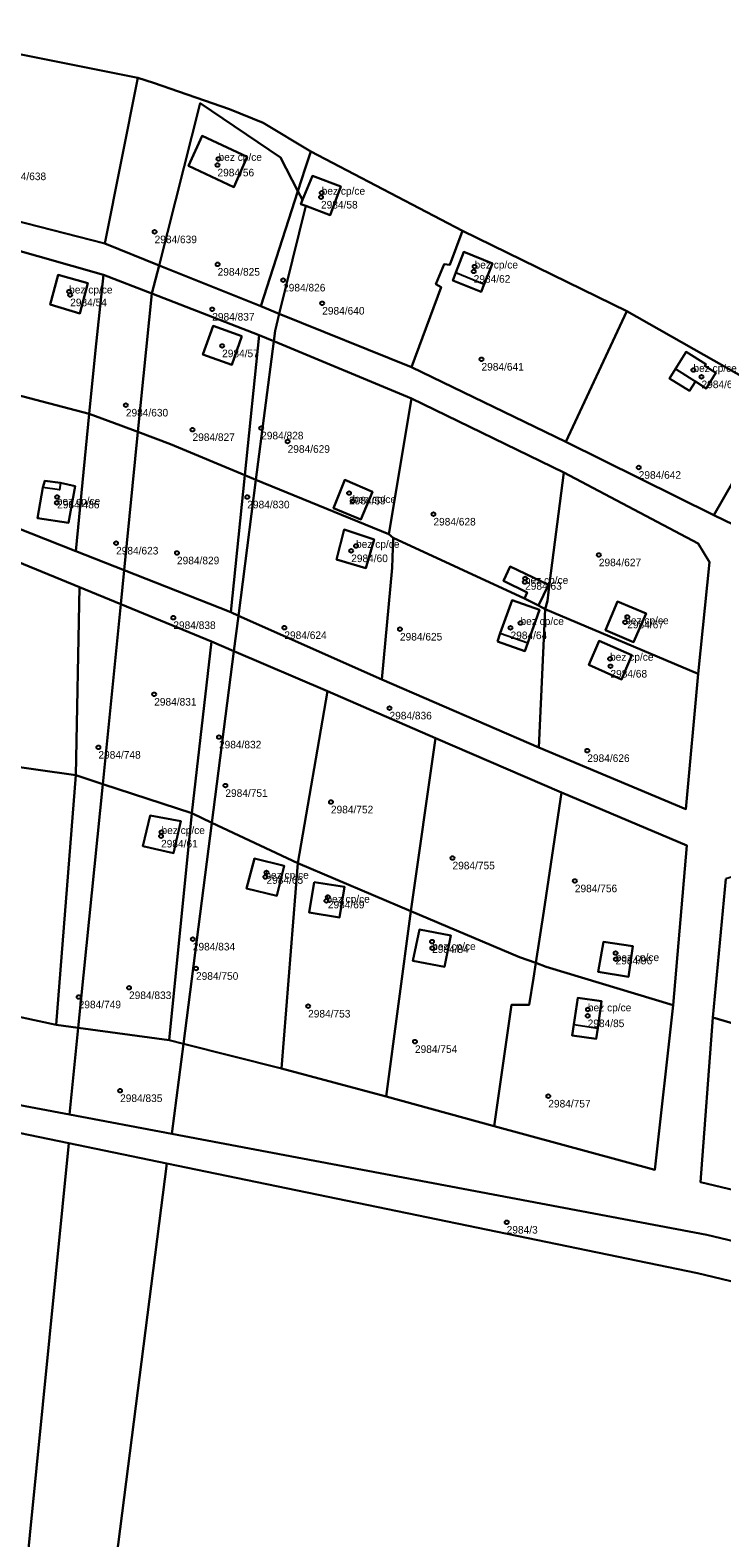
# Model space of a CAD drawing. Extents: x -878211 to -870363, y -1058464 to -1052522.
# Drawn here: x -873449 to -873357.8, y -1056219.7 to -1056021 of the extents above; entities that cross this region are included whole.
import ezdxf

# ---------------------------------------------------------------- set-up
doc = ezdxf.new("R2010")
doc.units = 0
for name, color, linetype in [('Definiční body', 7, 'Continuous'), ('Polygon budovy', 7, 'Continuous'), ('Polygon parcely', 7, 'Continuous')]:
    doc.layers.add(name, color=color, linetype=linetype)

msp = doc.modelspace()

# ---------------------------------------------------------------- linework, layer by layer
at = {"layer": 'Definiční body'}
for centre in [(-873424.28, -1056038.73994), (-873424.14, -1056037.93994), (-873410.54, -1056042.39994), (-873410.63, -1056042.97994), (-873432.57, -1056047.54994), (-873424.26, -1056051.82994), (-873390.38, -1056052.12994), (-873415.63, -1056053.90994), (-873390.5, -1056052.75994), (-873443.84, -1056055.41994), (-873443.7, -1056055.85994), (-873424.97, -1056057.74994), (-873410.47, -1056056.95994), (-873423.67, -1056062.57994), (-873389.47, -1056064.33994), (-873361.53, -1056065.75994), (-873360.46, -1056066.65994), (-873436.36, -1056070.38994), (-873427.57, -1056073.61994), (-873418.52, -1056073.40994), (-873415.03, -1056075.17994), (-873368.74, -1056078.59994), (-873445.42, -1056082.49994), (-873420.35, -1056082.49994), (-873406.93, -1056081.97994), (-873445.46, -1056083.26994), (-873406.46, -1056083.03994), (-873395.81, -1056084.75994), (-873437.65, -1056088.57994), (-873429.62, -1056089.86994), (-873406.65, -1056089.58994), (-873406.01, -1056088.94994), (-873374, -1056090.12994), (-873383.75, -1056093.69994), (-873383.72, -1056093.22994), (-873430.1, -1056098.39994), (-873370.25, -1056098.30994), (-873415.46, -1056099.71994), (-873400.22, -1056099.91994), (-873385.64, -1056099.73994), (-873384.33, -1056099.10994), (-873370.52, -1056099.00994), (-873372.52, -1056103.81994), (-873372.47, -1056104.79994), (-873432.62, -1056108.49994), (-873401.6, -1056110.31994), (-873424.08, -1056114.13994), (-873439.98, -1056115.48994), (-873375.52, -1056115.92994), (-873423.24, -1056120.52994), (-873409.32, -1056122.69994), (-873431.72, -1056127.19994), (-873431.66, -1056126.66994), (-873393.29, -1056130.07994), (-873417.82, -1056131.98994), (-873417.97, -1056132.56994), (-873377.16, -1056133.09994), (-873409.92, -1056135.72994), (-873409.73, -1056135.21994), (-873427.53, -1056140.76994), (-873395.99, -1056141.09994), (-873395.96, -1056141.95994), (-873371.79, -1056142.60994), (-873371.77, -1056143.41994), (-873427.11, -1056144.63994), (-873435.94, -1056147.17994), (-873442.58, -1056148.39994), (-873412.33, -1056149.60994), (-873375.44, -1056150.03994), (-873375.47, -1056150.87994), (-873398.24, -1056154.27994), (-873437.12, -1056160.74994), (-873380.66, -1056161.46994), (-873386.15, -1056178.08994)]:
    msp.add_circle(centre, 0.25, dxfattribs=at)
at = {"layer": 'Polygon budovy'}
for points in [[(-873426.3, -1056034.91), (-873428.08, -1056038.85), (-873422.13, -1056041.64), (-873420.36, -1056037.66)], [(-873408.01, -1056041.57), (-873411.76, -1056040.15), (-873413.05, -1056043.34), (-873413.27, -1056043.88), (-873412.64, -1056044.12), (-873409.43, -1056045.33)], [(-873391.81, -1056050.19), (-873392.86, -1056052.9), (-873389.11, -1056054.44), (-873388.03, -1056051.72)], [(-873446.34, -1056057.1), (-873442.45, -1056058.29), (-873441.39, -1056054.29), (-873445.29, -1056053.22)], [(-873363.9, -1056065.6), (-873361.25, -1056067.28), (-873359.85, -1056068.18), (-873358.56, -1056066.12), (-873360.04, -1056065.2), (-873359.9, -1056064.97), (-873362.5, -1056063.35)], [(-873408.99, -1056083.97), (-873405.36, -1056085.48), (-873403.84, -1056081.83), (-873407.47, -1056080.24)], [(-873448.03, -1056085.3), (-873443.91, -1056085.92), (-873443.03, -1056081.08), (-873444.97, -1056080.64), (-873445.11, -1056081.57), (-873447.32, -1056081.25)], [(-873408.59, -1056090.71), (-873404.74, -1056091.86), (-873403.64, -1056088.08), (-873407.56, -1056086.78)], [(-873386.55, -1056093.54), (-873383.43, -1056095.07), (-873383.82, -1056095.88), (-873381.97, -1056096.79), (-873380.63, -1056094.06), (-873385.7, -1056091.64)], [(-873385.42, -1056096.08), (-873386.99, -1056100.42), (-873383.36, -1056101.71), (-873381.81, -1056097.37)], [(-873371.52, -1056096.27), (-873373.12, -1056100.05), (-873369.45, -1056101.62), (-873367.78, -1056097.85)], [(-873375.3, -1056104.63), (-873371.02, -1056106.55), (-873369.65, -1056103.34), (-873373.97, -1056101.47)], [(-873434.11, -1056128.52), (-873430.1, -1056129.46), (-873429.11, -1056125.24), (-873433.15, -1056124.46)], [(-873420.44, -1056134.09), (-873416.44, -1056135.07), (-873415.47, -1056131.09), (-873419.39, -1056130.13)], [(-873411.53, -1056133.24), (-873412.17, -1056137.27), (-873408.19, -1056137.9), (-873407.53, -1056133.87)], [(-873398.52, -1056143.62), (-873394.37, -1056144.43), (-873393.51, -1056140.29), (-873397.66, -1056139.48)], [(-873374.09, -1056145.07), (-873370.07, -1056145.72), (-873369.52, -1056141.71), (-873373.39, -1056141.11)], [(-873377.29, -1056152.02), (-873374.14, -1056152.5), (-873373.63, -1056148.96), (-873376.79, -1056148.51)]]:
    msp.add_lwpolyline(points, close=True, dxfattribs=at)
at = {"layer": 'Polygon parcely'}
for points in [[(-873422.69, -1056031.38), (-873418.27, -1056033.17), (-873411.98, -1056036.95), (-873406.26, -1056039.94), (-873391.99, -1056047.4), (-873370.31, -1056057.99), (-873349.99, -1056069.49), (-873346.78, -1056071.17), (-873338.98, -1056020.68), (-873404.93, -1055985.24), (-873484.29, -1055957.15), (-873490.94, -1056014.57), (-873481.86, -1056016.97), (-873478.93, -1056017.14), (-873462.56, -1056021.67), (-873456.37, -1056022.93), (-873434.77, -1056027.26), (-873432.72, -1056027.9)], [(-873434.77, -1056027.26), (-873456.37, -1056022.93), (-873459.94, -1056043.78), (-873439.13, -1056049.09)], [(-873415.99, -1056037.76), (-873413.67, -1056042.17), (-873412.71, -1056039.2), (-873411.98, -1056036.95), (-873418.27, -1056033.17), (-873422.69, -1056031.38), (-873432.72, -1056027.9), (-873434.77, -1056027.26), (-873439.13, -1056049.09), (-873431.99, -1056051.96), (-873426.56, -1056030.6)], [(-873431.99, -1056051.96), (-873418.57, -1056057.36), (-873413.67, -1056042.17), (-873415.99, -1056037.76), (-873426.56, -1056030.6)], [(-873420.36, -1056037.66), (-873422.13, -1056041.64), (-873428.08, -1056038.85), (-873426.3, -1056034.91)], [(-873420.36, -1056037.66), (-873426.3, -1056034.91), (-873428.08, -1056038.85), (-873422.13, -1056041.64)], [(-873416.14, -1056058.34), (-873398.7, -1056065.39), (-873394.77, -1056054.84), (-873395.51, -1056054.46), (-873394.38, -1056051.79), (-873393.64, -1056051.89), (-873391.99, -1056047.4), (-873406.26, -1056039.94), (-873411.98, -1056036.95), (-873412.71, -1056039.2), (-873413.67, -1056042.17), (-873413.05, -1056043.34), (-873411.76, -1056040.15), (-873408.01, -1056041.57), (-873409.43, -1056045.33), (-873412.64, -1056044.12)], [(-873408.01, -1056041.57), (-873411.76, -1056040.15), (-873413.05, -1056043.34), (-873413.27, -1056043.88), (-873412.64, -1056044.12), (-873409.43, -1056045.33)], [(-873416.14, -1056058.34), (-873412.64, -1056044.12), (-873413.27, -1056043.88), (-873413.05, -1056043.34), (-873413.67, -1056042.17), (-873418.57, -1056057.36)], [(-873462.32, -1056065.98), (-873441.18, -1056071.55), (-873440.36, -1056063.12), (-873439.31, -1056053.22), (-873452.14, -1056049.56), (-873461.05, -1056047.58)], [(-873378.35, -1056075.24), (-873370.31, -1056057.99), (-873391.99, -1056047.4), (-873393.64, -1056051.89), (-873394.38, -1056051.79), (-873395.51, -1056054.46), (-873394.77, -1056054.84), (-873398.7, -1056065.39)], [(-873392.86, -1056052.9), (-873393.27, -1056053.95), (-873389.53, -1056055.45), (-873389.11, -1056054.44), (-873388.03, -1056051.72), (-873391.81, -1056050.19)], [(-873392.86, -1056052.9), (-873391.81, -1056050.19), (-873388.03, -1056051.72), (-873389.11, -1056054.44), (-873389.53, -1056055.45), (-873393.27, -1056053.95)], [(-873431.99, -1056051.96), (-873432.94, -1056055.69), (-873418.77, -1056061.17), (-873416.87, -1056061.96), (-873416.69, -1056060.61), (-873416.14, -1056058.34), (-873418.57, -1056057.36)], [(-873442.45, -1056058.29), (-873441.39, -1056054.29), (-873445.29, -1056053.22), (-873446.34, -1056057.1)], [(-873442.45, -1056058.29), (-873446.34, -1056057.1), (-873445.29, -1056053.22), (-873441.39, -1056054.29)], [(-873432.94, -1056055.69), (-873439.31, -1056053.22), (-873440.36, -1056063.12), (-873441.18, -1056071.55), (-873437.04, -1056073.08), (-873434.77, -1056073.92)], [(-873430.48, -1056075.51), (-873420.67, -1056079.63), (-873418.77, -1056061.17), (-873432.94, -1056055.69), (-873434.77, -1056073.92)], [(-873358.84, -1056084.87), (-873349.99, -1056069.49), (-873370.31, -1056057.99), (-873378.35, -1056075.24)], [(-873421.06, -1056061.28), (-873422.39, -1056065.07), (-873426.21, -1056063.73), (-873424.85, -1056059.93)], [(-873421.06, -1056061.28), (-873424.85, -1056059.93), (-873426.21, -1056063.73), (-873422.39, -1056065.07)], [(-873416.87, -1056061.96), (-873418.77, -1056061.17), (-873420.67, -1056079.63), (-873419.21, -1056080.22)], [(-873419.21, -1056080.22), (-873401.69, -1056087.38), (-873398.68, -1056069.49), (-873416.87, -1056061.96)], [(-873362.06, -1056068.5), (-873361.25, -1056067.28), (-873359.85, -1056068.18), (-873358.56, -1056066.12), (-873360.04, -1056065.2), (-873359.9, -1056064.97), (-873362.5, -1056063.35), (-873363.9, -1056065.6), (-873364.7, -1056066.88)], [(-873362.06, -1056068.5), (-873364.7, -1056066.88), (-873363.9, -1056065.6), (-873362.5, -1056063.35), (-873359.9, -1056064.97), (-873360.04, -1056065.2), (-873358.56, -1056066.12), (-873359.85, -1056068.18), (-873361.25, -1056067.28)], [(-873442.94, -1056089.64), (-873441.18, -1056071.55), (-873462.32, -1056065.98), (-873463.51, -1056082.72), (-873454.79, -1056084.97)], [(-873398.68, -1056069.49), (-873401.69, -1056087.38), (-873401.1, -1056087.89), (-873383.82, -1056095.88), (-873383.43, -1056095.07), (-873386.55, -1056093.54), (-873385.7, -1056091.64), (-873380.63, -1056094.06), (-873381.97, -1056096.79), (-873381.06, -1056097.29), (-873380.75, -1056096.18), (-873380.51, -1056093.91), (-873378.63, -1056079.28)], [(-873337.83, -1056095.04), (-873331.06, -1056079.42), (-873346.78, -1056071.17), (-873349.99, -1056069.49), (-873358.84, -1056084.87)], [(-873434.77, -1056073.92), (-873437.04, -1056073.08), (-873441.18, -1056071.55), (-873442.94, -1056089.64), (-873436.59, -1056092.14)], [(-873422.53, -1056097.69), (-873420.67, -1056079.63), (-873430.48, -1056075.51), (-873434.77, -1056073.92), (-873436.59, -1056092.14)], [(-873421.52, -1056098.14), (-873419.21, -1056080.22), (-873420.67, -1056079.63), (-873422.53, -1056097.69)], [(-873402.61, -1056106.54), (-873401.24, -1056091.84), (-873401.1, -1056087.89), (-873401.69, -1056087.38), (-873419.21, -1056080.22), (-873421.52, -1056098.14)], [(-873403.84, -1056081.83), (-873407.47, -1056080.24), (-873408.99, -1056083.97), (-873405.36, -1056085.48)], [(-873403.84, -1056081.83), (-873405.36, -1056085.48), (-873408.99, -1056083.97), (-873407.47, -1056080.24)], [(-873378.63, -1056079.28), (-873380.51, -1056093.91), (-873380.75, -1056096.18), (-873381.06, -1056097.29), (-873360.89, -1056105.82), (-873359.39, -1056091.1), (-873360.91, -1056088.64)], [(-873447.32, -1056081.25), (-873448.03, -1056085.3), (-873443.91, -1056085.92), (-873443.03, -1056081.08), (-873444.97, -1056080.64), (-873447.04, -1056080.36)], [(-873447.32, -1056081.25), (-873447.04, -1056080.36), (-873444.97, -1056080.64), (-873443.03, -1056081.08), (-873443.91, -1056085.92), (-873448.03, -1056085.3)], [(-873442.49, -1056094.37), (-873458.04, -1056088), (-873458.51, -1056116.98), (-873442.96, -1056119.18)], [(-873408.59, -1056090.71), (-873404.74, -1056091.86), (-873403.64, -1056088.08), (-873407.56, -1056086.78)], [(-873408.59, -1056090.71), (-873407.56, -1056086.78), (-873403.64, -1056088.08), (-873404.74, -1056091.86)], [(-873381.92, -1056115.5), (-873381.06, -1056097.29), (-873381.97, -1056096.79), (-873383.82, -1056095.88), (-873401.1, -1056087.89), (-873401.24, -1056091.84), (-873402.61, -1056106.54)], [(-873436.59, -1056092.14), (-873437.04, -1056096.61), (-873425.07, -1056101.54), (-873422.12, -1056102.8), (-873421.52, -1056098.14), (-873422.53, -1056097.69)], [(-873381.97, -1056096.79), (-873380.63, -1056094.06), (-873385.7, -1056091.64), (-873386.55, -1056093.54), (-873383.43, -1056095.07), (-873383.82, -1056095.88)], [(-873437.04, -1056096.61), (-873442.49, -1056094.37), (-873442.96, -1056119.18), (-873439.41, -1056120.34)], [(-873387.38, -1056101.54), (-873383.76, -1056102.81), (-873383.36, -1056101.71), (-873381.81, -1056097.37), (-873385.42, -1056096.08), (-873386.99, -1056100.42)], [(-873387.38, -1056101.54), (-873386.99, -1056100.42), (-873385.42, -1056096.08), (-873381.81, -1056097.37), (-873383.36, -1056101.71), (-873383.76, -1056102.81)], [(-873437.04, -1056096.61), (-873439.41, -1056120.34), (-873427.68, -1056124.17), (-873425.07, -1056101.54)], [(-873362.52, -1056123.64), (-873360.89, -1056105.82), (-873381.06, -1056097.29), (-873381.92, -1056115.5)], [(-873369.45, -1056101.62), (-873367.78, -1056097.85), (-873371.52, -1056096.27), (-873373.12, -1056100.05)], [(-873369.45, -1056101.62), (-873373.12, -1056100.05), (-873371.52, -1056096.27), (-873367.78, -1056097.85)], [(-873425.07, -1056101.54), (-873427.68, -1056124.17), (-873425.02, -1056125.42), (-873422.12, -1056102.8)], [(-873369.65, -1056103.34), (-873373.97, -1056101.47), (-873375.3, -1056104.63), (-873371.02, -1056106.55)], [(-873369.65, -1056103.34), (-873371.02, -1056106.55), (-873375.3, -1056104.63), (-873373.97, -1056101.47)], [(-873425.02, -1056125.42), (-873413.67, -1056130.74), (-873409.76, -1056108.09), (-873422.12, -1056102.8)], [(-873395.55, -1056114.3), (-873409.76, -1056108.09), (-873413.67, -1056130.74), (-873398.79, -1056137.09)], [(-873378.93, -1056121.46), (-873395.55, -1056114.3), (-873398.79, -1056137.09), (-873384.46, -1056143.13), (-873382.31, -1056143.9), (-873381.24, -1056137.09)], [(-873442.96, -1056119.18), (-873458.51, -1056116.98), (-873459.02, -1056149.18), (-873445.53, -1056152.08)], [(-873439.41, -1056120.34), (-873442.96, -1056119.18), (-873445.53, -1056152.08), (-873442.63, -1056152.47)], [(-873430.63, -1056154.1), (-873427.68, -1056124.17), (-873439.41, -1056120.34), (-873442.63, -1056152.47)], [(-873378.93, -1056121.46), (-873381.24, -1056137.09), (-873382.31, -1056143.9), (-873380.93, -1056144.4), (-873364.2, -1056149.49), (-873362.41, -1056128.41)], [(-873434.11, -1056128.52), (-873433.15, -1056124.46), (-873429.11, -1056125.24), (-873430.1, -1056129.46)], [(-873434.11, -1056128.52), (-873430.1, -1056129.46), (-873429.11, -1056125.24), (-873433.15, -1056124.46)], [(-873428.77, -1056154.57), (-873425.02, -1056125.42), (-873427.68, -1056124.17), (-873430.63, -1056154.1)], [(-873413.67, -1056130.74), (-873425.02, -1056125.42), (-873428.77, -1056154.57), (-873415.82, -1056157.83)], [(-873419.39, -1056130.13), (-873420.44, -1056134.09), (-873416.44, -1056135.07), (-873415.47, -1056131.09)], [(-873419.39, -1056130.13), (-873415.47, -1056131.09), (-873416.44, -1056135.07), (-873420.44, -1056134.09)], [(-873402.06, -1056161.52), (-873398.79, -1056137.09), (-873413.67, -1056130.74), (-873415.82, -1056157.83)], [(-873411.53, -1056133.24), (-873412.17, -1056137.27), (-873408.19, -1056137.9), (-873407.53, -1056133.87)], [(-873411.53, -1056133.24), (-873407.53, -1056133.87), (-873408.19, -1056137.9), (-873412.17, -1056137.27)], [(-873357.25, -1056132.82), (-873358.95, -1056151.09), (-873335.96, -1056157.88), (-873333.51, -1056140.43), (-873352.16, -1056133.09), (-873355.68, -1056132.36)], [(-873387.78, -1056165.44), (-873385.52, -1056149.44), (-873383.18, -1056149.42), (-873382.63, -1056145.93), (-873382.31, -1056143.9), (-873384.46, -1056143.13), (-873398.79, -1056137.09), (-873402.06, -1056161.52)], [(-873397.66, -1056139.48), (-873398.52, -1056143.62), (-873394.37, -1056144.43), (-873393.51, -1056140.29)], [(-873397.66, -1056139.48), (-873393.51, -1056140.29), (-873394.37, -1056144.43), (-873398.52, -1056143.62)], [(-873369.52, -1056141.71), (-873373.39, -1056141.11), (-873374.09, -1056145.07), (-873370.07, -1056145.72)], [(-873369.52, -1056141.71), (-873370.07, -1056145.72), (-873374.09, -1056145.07), (-873373.39, -1056141.11)], [(-873366.62, -1056171.17), (-873364.2, -1056149.49), (-873380.93, -1056144.4), (-873382.31, -1056143.9), (-873382.63, -1056145.93), (-873383.18, -1056149.42), (-873385.52, -1056149.44), (-873387.78, -1056165.44)], [(-873377.29, -1056152.02), (-873377.51, -1056153.47), (-873374.35, -1056153.93), (-873374.14, -1056152.5), (-873373.63, -1056148.96), (-873376.79, -1056148.51)], [(-873377.29, -1056152.02), (-873376.79, -1056148.51), (-873373.63, -1056148.96), (-873374.14, -1056152.5), (-873374.35, -1056153.93), (-873377.51, -1056153.47)], [(-873360.59, -1056172.8), (-873339.38, -1056177.87), (-873335.96, -1056157.88), (-873358.95, -1056151.09)], [(-873430.29, -1056166.44), (-873428.77, -1056154.57), (-873430.63, -1056154.1), (-873442.63, -1056152.47), (-873443.77, -1056163.9)], [(-873467.08, -1056323.48), (-873452.41, -1056327.48), (-873445.56, -1056284.55), (-873430.95, -1056170.33), (-873443.87, -1056167.66), (-873455.89, -1056287.77)]]:
    msp.add_lwpolyline(points, close=True, dxfattribs=at)
for points in [[(-873452.14, -1056049.56), (-873439.31, -1056053.22), (-873432.94, -1056055.69), (-873431.99, -1056051.96), (-873439.13, -1056049.09), (-873459.94, -1056043.78)], [(-873337.83, -1056095.04), (-873358.84, -1056084.87), (-873378.35, -1056075.24), (-873398.7, -1056065.39), (-873416.14, -1056058.34), (-873416.69, -1056060.61), (-873416.87, -1056061.96), (-873398.68, -1056069.49), (-873378.63, -1056079.28), (-873360.91, -1056088.64), (-873359.39, -1056091.1), (-873360.89, -1056105.82), (-873362.52, -1056123.64), (-873381.92, -1056115.5), (-873402.61, -1056106.54), (-873421.52, -1056098.14), (-873422.12, -1056102.8), (-873409.76, -1056108.09), (-873395.55, -1056114.3), (-873378.93, -1056121.46), (-873362.41, -1056128.41), (-873364.2, -1056149.49), (-873366.62, -1056171.17), (-873387.78, -1056165.44), (-873402.06, -1056161.52), (-873415.82, -1056157.83), (-873428.77, -1056154.57), (-873430.29, -1056166.44), (-873359.74, -1056179.73), (-873316.94, -1056189.94)], [(-873458.04, -1056088), (-873442.49, -1056094.37), (-873437.04, -1056096.61), (-873436.59, -1056092.14), (-873442.94, -1056089.64), (-873454.79, -1056084.97)], [(-873233.13, -1056211.3), (-873258.39, -1056203.81), (-873288.18, -1056196.8), (-873300.97, -1056193.75), (-873316.94, -1056189.94), (-873359.74, -1056179.73), (-873430.29, -1056166.44), (-873443.77, -1056163.9), (-873536.08, -1056146.51), (-873579.25, -1056137.66), (-873583.21, -1056136.78), (-873640.57, -1056126.39), (-873663.43, -1056120.04), (-873669.67, -1056117.9), (-873683.77, -1056104.56), (-873698.77, -1056094.59), (-873705.76, -1056091.7), (-873717.22, -1056089.4), (-873720.7, -1056089.42), (-873762.63, -1056089.66), (-873840.34, -1056089.55), (-873878.08, -1056089.5)], [(-873339.38, -1056177.87), (-873360.59, -1056172.8), (-873358.95, -1056151.09), (-873357.25, -1056132.82)], [(-873603.98, -1056138.97), (-873580.66, -1056143.3), (-873536.99, -1056151.43), (-873510.04, -1056156.4), (-873469.01, -1056162.46), (-873443.87, -1056167.66), (-873430.95, -1056170.33), (-873360.98, -1056184.79), (-873317.75, -1056195.16), (-873301.81, -1056198.98), (-873289.4, -1056201.96), (-873278.56, -1056204.51), (-873259.87, -1056208.9), (-873253.05, -1056210.89), (-873234.74, -1056216.24), (-873228.37, -1056218.32)], [(-873455.89, -1056287.77), (-873443.87, -1056167.66), (-873469.01, -1056162.46), (-873510.04, -1056156.4), (-873536.99, -1056151.43), (-873580.66, -1056143.3), (-873577.84, -1056230.12)], [(-873536.08, -1056146.51), (-873443.77, -1056163.9), (-873442.63, -1056152.47), (-873445.53, -1056152.08), (-873459.02, -1056149.18)], [(-873325.31, -1056243.71), (-873317.75, -1056195.16), (-873360.98, -1056184.79), (-873430.95, -1056170.33), (-873445.56, -1056284.55)]]:
    msp.add_lwpolyline(points, dxfattribs=at)

# ---------------------------------------------------------------- texts
at = {"layer": 'Definiční body'}
for s, p in [('bez cp/ce', (-873424.14, -1056038.19)), ('2984/638', (-873452.45, -1056040.729)), ('2984/56', (-873424.28, -1056040.229)), ('bez cp/ce', (-873410.54, -1056042.649)), ('2984/58', (-873410.63, -1056044.469)), ('2984/639', (-873432.57, -1056049.039)), ('2984/825', (-873424.26, -1056053.319)), ('bez cp/ce', (-873390.38, -1056052.379)), ('2984/826', (-873415.63, -1056055.399)), ('2984/62', (-873390.5, -1056054.249)), ('bez cp/ce', (-873443.84, -1056055.669)), ('2984/54', (-873443.7, -1056057.349)), ('2984/837', (-873424.97, -1056059.239)), ('2984/640', (-873410.47, -1056058.449)), ('2984/57', (-873423.67, -1056064.069)), ('2984/641', (-873389.47, -1056065.829)), ('bez cp/ce', (-873361.53, -1056066.01)), ('2984/66', (-873360.46, -1056068.149)), ('2984/630', (-873436.36, -1056071.879)), ('2984/827', (-873427.57, -1056075.109)), ('2984/828', (-873418.52, -1056074.899)), ('2984/629', (-873415.03, -1056076.669)), ('2984/642', (-873368.74, -1056080.089)), ('bez cp/ce', (-873406.46, -1056083.29)), ('bez cp/ce', (-873445.46, -1056083.52)), ('2984/486', (-873445.42, -1056083.989)), ('2984/830', (-873420.35, -1056083.989)), ('2984/59', (-873406.93, -1056083.469)), ('2984/628', (-873395.81, -1056086.249)), ('bez cp/ce', (-873406.01, -1056089.2)), ('2984/623', (-873437.65, -1056090.069)), ('2984/60', (-873406.65, -1056091.079)), ('2984/829', (-873429.62, -1056091.359)), ('2984/627', (-873374, -1056091.619)), ('bez cp/ce', (-873383.75, -1056093.95)), ('2984/63', (-873383.72, -1056094.719)), ('2984/838', (-873430.1, -1056099.889)), ('2984/624', (-873415.46, -1056101.209)), ('bez cp/ce', (-873384.33, -1056099.36)), ('bez cp/ce', (-873370.52, -1056099.26)), ('2984/67', (-873370.25, -1056099.799)), ('2984/625', (-873400.22, -1056101.409)), ('2984/64', (-873385.64, -1056101.229)), ('bez cp/ce', (-873372.52, -1056104.07)), ('2984/68', (-873372.47, -1056106.289)), ('2984/831', (-873432.62, -1056109.989)), ('2984/836', (-873401.6, -1056111.809)), ('2984/748', (-873439.98, -1056116.979)), ('2984/832', (-873424.08, -1056115.629)), ('2984/626', (-873375.52, -1056117.419)), ('2984/751', (-873423.24, -1056122.019)), ('2984/752', (-873409.32, -1056124.189)), ('bez cp/ce', (-873431.66, -1056126.919)), ('2984/61', (-873431.72, -1056128.689)), ('bez cp/ce', (-873417.97, -1056132.82)), ('2984/755', (-873393.29, -1056131.569)), ('2984/65', (-873417.82, -1056133.479)), ('2984/756', (-873377.16, -1056134.589)), ('bez cp/ce', (-873409.92, -1056135.98)), ('2984/69', (-873409.73, -1056136.709)), ('2984/834', (-873427.53, -1056142.259)), ('2984/84', (-873395.99, -1056142.589)), ('bez cp/ce', (-873395.96, -1056142.21)), ('2984/96', (-873371.79, -1056144.099)), ('bez cp/ce', (-873371.77, -1056143.669)), ('2984/750', (-873427.11, -1056146.129)), ('2984/833', (-873435.94, -1056148.669)), ('2984/749', (-873442.58, -1056149.889)), ('bez cp/ce', (-873375.44, -1056150.29)), ('2984/753', (-873412.33, -1056151.099)), ('2984/85', (-873375.47, -1056152.369)), ('2984/754', (-873398.24, -1056155.769)), ('2984/835', (-873437.12, -1056162.239)), ('2984/757', (-873380.66, -1056162.959)), ('2984/3', (-873386.15, -1056179.579))]:
    msp.add_text(s, height=0.999996, dxfattribs=at).set_placement(p)

doc.saveas('drawing.dxf')
